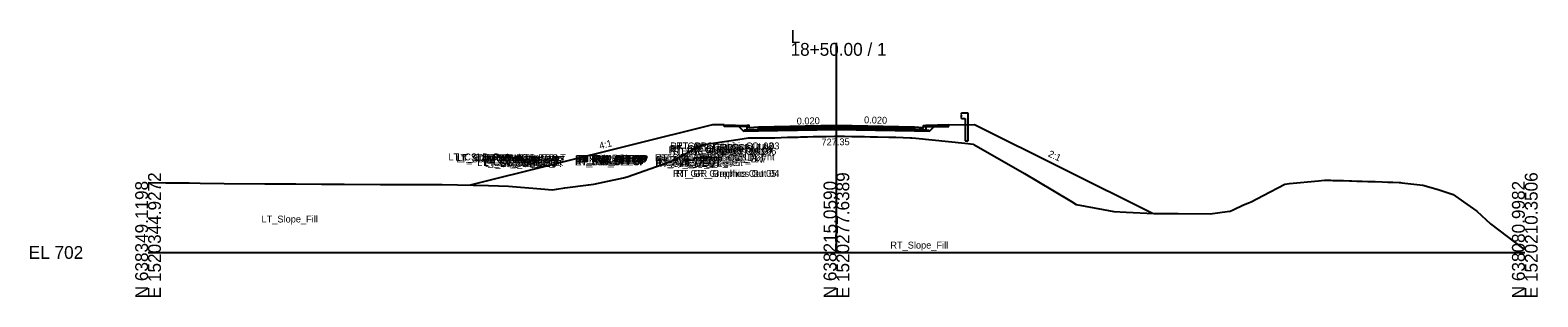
# Model space of a CAD drawing. Extents: x -26 to 3903, y -10 to 9531.
# Drawn here: x -25.7 to 302.8, y 8490.3 to 8548.5 of the extents above; entities that cross this region are included whole.
import ezdxf

# ---------------------------------------------------------------- set-up
doc = ezdxf.new("R2010")
doc.units = 0
for name, color, linetype in [('Default', 7, 'Continuous'), ('Exist Cross Section Cell', 7, 'Continuous'), ('Exist XS Center Line Elevation Label', 7, 'Continuous'), ('Exist XS Ground Line', 7, 'Continuous'), ('Old_Level_63', 7, 'Continuous'), ('Prop CMT Conc Surface', 7, 'Continuous'), ('Prop CMT Guardrail Graphics', 7, 'Continuous'), ('Prop CMT Pvmt Course 1', 7, 'Continuous'), ('Prop CMT Pvmt Course 1 CG', 7, 'Continuous'), ('Prop CMT Pvmt Course 2', 7, 'Continuous'), ('Prop CMT Pvmt Course 3', 7, 'Continuous'), ('Prop CMT Pvmt Surface', 7, 'Continuous'), ('Prop CMT Slope Grass', 7, 'Continuous'), ('Prop CMT Subgrade Earthwork', 7, 'Continuous'), ('Prop XS Finish Grade Concrete', 7, 'Continuous'), ('Prop XS SE Text', 7, 'Continuous'), ('Prop XS Side Slope Text', 7, 'Continuous')]:
    doc.layers.add(name, color=color, linetype=linetype)

msp = doc.modelspace()

# ---------------------------------------------------------------- linework, layer by layer
at = {"layer": 'Exist Cross Section Cell'}
for p, q in [((150, 8500), (150, 8545.71)), ((0, 8500), (150, 8500)), ((150, 8500), (300, 8500))]:
    msp.add_line(p, q, dxfattribs=at)
at = {"layer": 'Exist XS Ground Line'}
msp.add_lwpolyline([(0, 8515.24), (3.86, 8515.17), (8.95, 8515.17), (11.37, 8515.12), (16.59, 8515.08), (25.47, 8515), (32.18, 8514.95), (37.81, 8514.91), (42.74, 8514.89), (50.68, 8514.85), (61.83, 8514.81), (62.65, 8514.79), (64.08, 8514.8), (74.19, 8514.59), (78.53, 8514.44), (85.57, 8513.89), (88.1, 8513.64), (89, 8513.81), (90.85, 8514.1), (95.99, 8514.76), (97.16, 8514.9), (99.19, 8515.37), (103.61, 8516.3), (104.37, 8516.52), (110.76, 8518.75), (113.86, 8519.87), (115.12, 8520.49), (115.51, 8520.66), (116.56, 8521.23), (120.68, 8523.48), (127.6, 8524.5), (130.87, 8524.99), (132.84, 8525.01), (134.75, 8524.98), (135.06, 8524.99), (135.93, 8525.02), (136.57, 8525.04), (137.93, 8525.08), (139.36, 8525.12), (140.64, 8525.15), (141.65, 8525.18), (142.16, 8525.2), (143.69, 8525.23), (144.96, 8525.27), (146.21, 8525.29), (147.75, 8525.32), (149.59, 8525.35), (149.82, 8525.35), (149.82, 8525.35), (150.61, 8525.35), (150.94, 8525.35), (151.76, 8525.34), (153.33, 8525.33), (154.89, 8525.31), (156.11, 8525.29), (157.33, 8525.26), (158.92, 8525.22), (161.42, 8525.18), (161.89, 8525.17), (161.93, 8525.16), (162.92, 8525.12), (164.51, 8525.07), (166.12, 8525), (166.33, 8525), (166.41, 8524.99), (167.3, 8524.91), (177.99, 8523.81), (179.88, 8523.62), (179.94, 8523.58), (191.01, 8517.22), (193.66, 8515.59), (201.24, 8511.1), (202.26, 8510.46), (208.09, 8509.39), (210.41, 8508.94), (213.1, 8508.76), (219.13, 8508.53), (224.49, 8508.47), (231.46, 8508.46), (235.12, 8508.92), (235.82, 8509.02), (236.42, 8509.29), (238.67, 8510.42), (240.03, 8510.89), (240.37, 8511.02), (243, 8512.41), (247.69, 8514.91), (248.7, 8515.08), (255.05, 8515.61), (256.36, 8515.75), (256.81, 8515.78), (256.91, 8515.78), (257.73, 8515.75), (258.2, 8515.73), (259, 8515.7), (260.48, 8515.67), (261.8, 8515.63), (262.34, 8515.61), (263.4, 8515.57), (264.59, 8515.53), (265.77, 8515.5), (267.36, 8515.45), (268.92, 8515.4), (270.12, 8515.36), (271.19, 8515.33), (271.21, 8515.33), (272.65, 8515.26), (272.93, 8515.25), (273.19, 8515.22), (277.78, 8514.69), (281.15, 8513.74), (284.41, 8512.64), (286.65, 8511.08), (289.57, 8509), (292.54, 8506.25), (299.48, 8500.93), (300, 8500.87)], dxfattribs=at)
at = {"layer": 'Old_Level_63'}
for p, q in [((131, 8527.22), (131, 8527.72)), ((133, 8527.34), (131, 8527.22)), ((169, 8527.22), (167, 8527.34)), ((169, 8527.72), (169, 8527.22))]:
    msp.add_line(p, q, dxfattribs=at)
for points in [[(125.5, 8527.82), (130.5, 8527.72)], [(125.5, 8527.49), (125.5, 8527.82)], [(130.5, 8527.39), (125.5, 8527.49)], [(130.5, 8527.72), (130.5, 8526.71), (133, 8526.76)], [(133, 8526.76), (133, 8527.34)], [(169.5, 8527.72), (169.5, 8526.71), (167, 8526.76)], [(167, 8526.76), (167, 8527.34)], [(169.5, 8527.41), (174.5, 8527.5)], [(174.5, 8527.5), (174.5, 8527.82)]]:
    msp.add_lwpolyline(points, dxfattribs=at)
at = {"layer": 'Prop CMT Conc Surface'}
for points in [[(130.5, 8527.66), (125.5, 8527.76)], [(131, 8527.15), (131, 8527.65), (130.5, 8527.65)], [(133, 8527.27), (131, 8527.15)], [(167, 8527.27), (169, 8527.15)], [(169, 8527.15), (169, 8527.65), (169.5, 8527.65)], [(169.5, 8527.66), (174.5, 8527.76)], [(80.5, 8520.66), (75.5, 8520.76)], [(81, 8520.15), (81, 8520.65), (80.5, 8520.65)], [(83, 8520.27), (81, 8520.15)], [(117, 8520.27), (119, 8520.15)], [(119, 8520.15), (119, 8520.65), (119.5, 8520.65)], [(119.5, 8520.66), (124.5, 8520.76)]]:
    msp.add_lwpolyline(points, dxfattribs=at)
at = {"layer": 'Prop CMT Guardrail Graphics'}
for points in [[(178.69, 8530.37), (177.36, 8530.37), (177.09, 8530.08)], [(177.09, 8530.08), (177.36, 8529.79)], [(177.36, 8529.79), (177.09, 8529.5)], [(177.09, 8529.5), (177.36, 8529.21), (178.03, 8529.21)], [(178.03, 8529.21), (178.03, 8524.37)], [(178.69, 8524.37), (178.69, 8530.37)], [(178.03, 8524.37), (178.69, 8524.37)]]:
    msp.add_lwpolyline(points, dxfattribs=at)
at = {"layer": 'Prop CMT Pvmt Course 1'}
for points in [[(150, 8527.68), (133, 8527.34)], [(133, 8527.09), (150, 8527.43)], [(133, 8527.34), (133, 8527.09)], [(150, 8527.43), (150, 8527.68)], [(150, 8527.68), (167, 8527.34)], [(150, 8527.43), (150, 8527.68)], [(167, 8527.09), (150, 8527.43)], [(167, 8527.34), (167, 8527.09)]]:
    msp.add_lwpolyline(points, dxfattribs=at)
msp.add_lwpolyline([(150, 8527.43), (150, 8527.56), (150, 8527.56), (150, 8527.43)], close=True, dxfattribs=at)
msp.add_lwpolyline([(150, 8527.43), (150, 8527.56), (150, 8527.56), (150, 8527.43)], close=True, dxfattribs=at)
at = {"layer": 'Prop CMT Pvmt Course 1 CG'}
for points in [[(133, 8526.76), (130, 8526.7), (129.74, 8526.45)], [(129.74, 8526.45), (133, 8526.51)], [(133, 8526.51), (133, 8526.76)], [(167, 8526.76), (170, 8526.7), (170.26, 8526.45)], [(167, 8526.51), (167, 8526.76)], [(170.26, 8526.45), (167, 8526.51)]]:
    msp.add_lwpolyline(points, dxfattribs=at)
at = {"layer": 'Prop CMT Pvmt Course 2'}
for points in [[(150, 8527.43), (133, 8527.09)], [(133, 8526.76), (150, 8527.1)], [(133, 8527.09), (133, 8526.76)], [(150, 8527.1), (150, 8527.43)], [(150, 8527.1), (150, 8527.43)], [(150, 8527.43), (167, 8527.09)], [(167, 8526.76), (150, 8527.1)], [(167, 8527.09), (167, 8526.76)]]:
    msp.add_lwpolyline(points, dxfattribs=at)
at = {"layer": 'Prop CMT Pvmt Course 3'}
for points in [[(150, 8527.1), (133, 8526.76)], [(133, 8526.51), (150, 8526.85)], [(133, 8526.76), (133, 8526.51)], [(150, 8526.85), (150, 8527.1)], [(150, 8527.1), (167, 8526.76)], [(150, 8526.85), (150, 8527.1)], [(167, 8526.51), (150, 8526.85)], [(167, 8526.76), (167, 8526.51)]]:
    msp.add_lwpolyline(points, dxfattribs=at)
at = {"layer": 'Prop CMT Pvmt Surface'}
for p, q in [((150, 8527.68), (133, 8527.34)), ((167, 8527.34), (150, 8527.68))]:
    msp.add_line(p, q, dxfattribs=at)
for points in [[(150, 8527.68), (133, 8527.34)], [(150, 8527.68), (167, 8527.34)]]:
    msp.add_lwpolyline(points, dxfattribs=at)
at = {"layer": 'Prop CMT Slope Grass'}
for p, q in [((123, 8527.87), (70.2, 8514.68)), ((180.09, 8527.94), (218.89, 8508.54))]:
    msp.add_line(p, q, dxfattribs=at)
for points in [[(125.5, 8527.82), (123, 8527.87)], [(174.5, 8527.82), (180.09, 8527.94)]]:
    msp.add_lwpolyline(points, dxfattribs=at)
at = {"layer": 'Prop CMT Subgrade Earthwork'}
for points in [[(133, 8526.51), (129.74, 8526.45), (128.43, 8527.77)], [(150, 8526.85), (133, 8526.51)], [(150, 8526.85), (167, 8526.51)], [(167, 8526.51), (170.26, 8526.45), (171.57, 8527.77)]]:
    msp.add_lwpolyline(points, dxfattribs=at)
at = {"layer": 'Prop XS Finish Grade Concrete'}
for points in [[(125.5, 8527.82), (130.5, 8527.72)], [(133, 8527.34), (131, 8527.22), (131, 8527.72), (130.5, 8527.72)], [(167, 8527.34), (169, 8527.22), (169, 8527.72), (169.5, 8527.72)], [(174.5, 8527.82), (169.5, 8527.72)]]:
    msp.add_lwpolyline(points, dxfattribs=at)

# ---------------------------------------------------------------- texts
at = {"layer": 'Default'}
msp.add_text('-', height=0.0001, dxfattribs=at).set_placement((0, 8500))
at = {"layer": 'Exist Cross Section Cell'}
for s, p in [('L', (140, 8545.71)), ('18+50.00 / 1', (140, 8542.91)), ('EL 702', (-26, 8498.6))]:
    msp.add_text(s, height=2.8, dxfattribs=at).set_placement(p)
for s, p in [('E 1520344.9272', (2.8, 8490)), ('E 1520277.6389', (152.8, 8490)), ('E 1520210.3506', (302.8, 8490)), ('N 638349.1198', (0, 8490)), ('N 638215.0590', (150, 8490)), ('N 638080.9982', (300, 8490))]:
    msp.add_text(s, height=2.8, rotation=90, dxfattribs=at).set_placement(p)
at = {"layer": 'Exist XS Center Line Elevation Label'}
msp.add_text('727.35', height=1.5, rotation=0.8401, dxfattribs=at).set_placement((146.75, 8523.32))
at = {"layer": 'Prop CMT Conc Surface'}
for s, p in [('RT_GR_Graphics Out 08', (113.44, 8521.62)), ('RT_GR_Graphics Out 07', (113.69, 8521.33)), ('RT_GR_Graphics Out 09', (113.72, 8521.91)), ('RT_GR_Graphics Out 02', (113.76, 8522.49)), ('RT_GR_Graphics Out 06', (114.38, 8521.33)), ('RT_GR_Graphics Out 03', (115.06, 8522.49)), ('RT_GR_Out', (119.29, 8522.2)), ('LT_CSLP_Pnt', (65.45, 8520.09)), ('LT_SDWK_Out_Top', (66.94, 8520.01)), ('LT_SDWK_Out_Bot', (67.12, 8519.67)), ('LT_Sub_Trench_Out_DLT', (67.4, 8519.94)), ('LT_CG1_Shelf_Out', (71.73, 8518.87)), ('LT_SDWK_In_Top', (72.8, 8519.91)), ('LT_CG_Top_BOC', (72.86, 8519.9)), ('LT_SDWK_In_Bot', (72.99, 8519.57)), ('LT_CG_Bot_BOC', (73.07, 8518.88)), ('LT_CG_Top_Face', (73.38, 8519.9)), ('LT_Sub_OEOP', (73.39, 8518.62)), ('LT_CG_Top_Gut', (73.78, 8519.4)), ('LT_PV2_OEOT', (76.62, 8519.27)), ('LT_PV3_OEOT', (76.62, 8518.93)), ('LT_Sub_OEOT', (76.65, 8518.68)), ('LT_PV1_OEOT', (76.8, 8519.52)), ('LT_CG_Bot_IE', (76.88, 8518.93)), ('RT_PV2_OEEOP', (93, 8519.61)), ('RT_PV3_OEEOP', (93, 8519.27)), ('RT_Sub_OEEOP', (93.04, 8519.02)), ('LT_PV2_OEEOP', (93.09, 8519.61)), ('LT_PV3_OEEOP', (93.09, 8519.27)), ('LT_Sub_OEEOP', (93.12, 8519.02)), ('RT_PV1_OEEOP', (93.18, 8519.73)), ('LT_PV1_OEEOP', (93.27, 8519.73)), ('RT_PV2_IEEOP', (93.57, 8519.61)), ('LT_PV2_IEEOP', (93.66, 8519.61)), ('RT_PV1_IEEOP', (93.75, 8519.73)), ('LT_PV1_IEEOP', (93.84, 8519.73)), ('PV2_PGL', (96.03, 8519.61)), ('PV1_PGL', (96.2, 8519.86)), ('RT_Sub_Trench_Out_DLT', (110.46, 8519.94)), ('RT_PV2_OEOT', (110.53, 8519.27)), ('RT_PV3_OEOT', (110.53, 8518.93)), ('RT_Sub_OEOT', (110.56, 8518.68)), ('RT_PV1_OEOT', (110.71, 8519.52)), ('RT_CG_Bot_IE', (110.79, 8518.93)), ('RT_CG_Top_Face', (111.29, 8519.9)), ('RT_CG1_Shelf_Out', (111.64, 8518.87)), ('RT_CG_Top_Gut', (111.69, 8519.4)), ('RT_SDWK_In_Top', (111.71, 8519.91)), ('RT_CG_Top_BOC', (111.77, 8519.9)), ('RT_SDWK_In_Bot', (111.9, 8519.57)), ('RT_CG_Bot_BOC', (111.98, 8518.88)), ('RT_Sub_OEOP', (113.81, 8518.62)), ('RT_SDWK_Out_Top', (115.85, 8520.01)), ('RT_SDWK_Out_Bot', (116.03, 8519.67)), ('RT_CSLP_Pnt', (123.36, 8520.09)), ('RT_GR_Graphics Out 05', (114.39, 8516.49)), ('RT_GR_Graphics Out 04', (115.04, 8516.49)), ('LT_Slope_Fill', (24.73, 8506.54)), ('RT_Slope_Fill', (161.75, 8500.85))]:
    msp.add_text(s, height=1.5, dxfattribs=at).set_placement(p)
at = {"layer": 'Prop XS SE Text'}
for rotation, p in [(1.1458, (141.36, 8527.9)), (358.8542, (156.01, 8528.18))]:
    msp.add_text('0.020', height=1.5, rotation=rotation, dxfattribs=at).set_placement(p)
at = {"layer": 'Prop XS Side Slope Text'}
for s, rotation, p in [('4:1', 14.0362, (98.5, 8522.5)), ('2:1', 334.8977, (195.98, 8521.01))]:
    msp.add_text(s, height=1.5, rotation=rotation, dxfattribs=at).set_placement(p)

doc.saveas('drawing.dxf')
